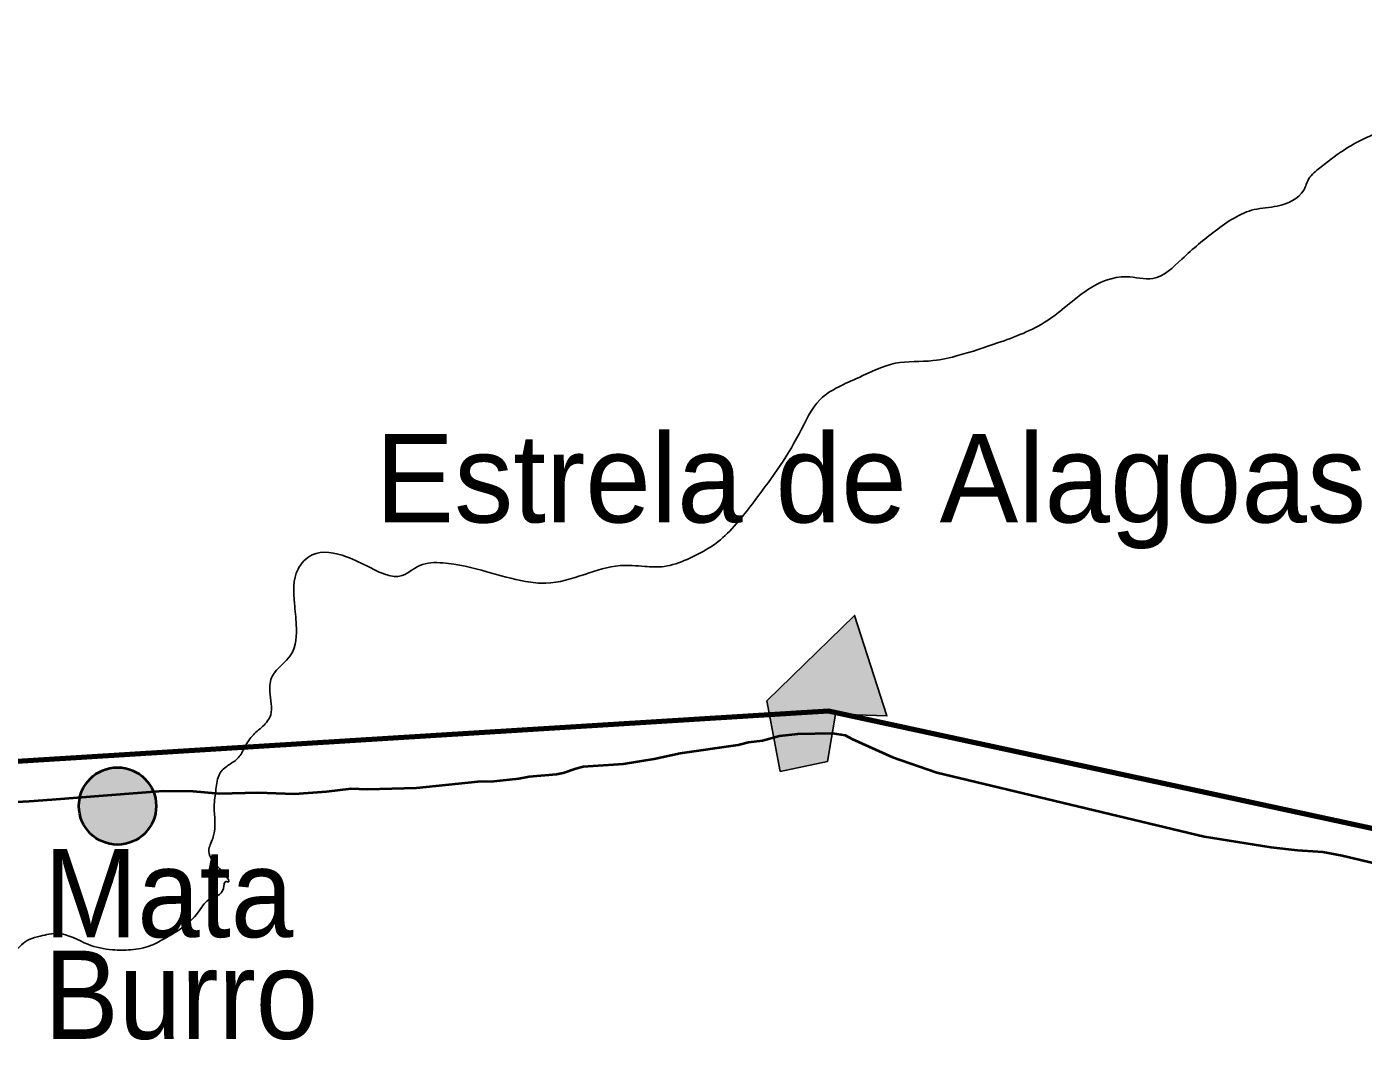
# Model space of a CAD drawing. Extents: x 553962 to 842807, y 8883888 to 9032388.
# Drawn here: x 740163 to 747736, y 8959924 to 8965692 of the extents above; entities that cross this region are included whole.
import ezdxf

# ---------------------------------------------------------------- set-up
doc = ezdxf.new("R2010")
doc.units = 0
doc.header["$LTSCALE"] = 200
for name, color, linetype, lineweight in [('12', 7, 'Continuous', 25), ('21', 7, 'Continuous', 25), ('24', 7, 'Continuous', 25), ('28', 7, 'Continuous', 40), ('41', 7, 'Continuous', 40)]:
    doc.layers.add(name, color=color, linetype=linetype, lineweight=lineweight)

msp = doc.modelspace()

# ---------------------------------------------------------------- hatches: boundary and pattern name
at = {"layer": '21'}
msp.add_hatch(color=256, dxfattribs=at).paths.add_polyline_path([(744356.4, 8961874.7), (744853, 8962358.3), (745037.2, 8961789.1), (744746.3, 8961798.3), (744699.8, 8961530.9), (744432.2, 8961475.3)])
at = {"layer": '41'}
msp.add_hatch(color=256, dxfattribs=at).paths.add_polyline_path([(740896.4, 8961278.9, 1), (740458.8, 8961278.9, 1)])

# ---------------------------------------------------------------- linework, layer by layer
at = {"layer": '12', "lineweight": 40}
for points in [[(740936, 8961365.4), (741106, 8961363.1), (741255.2, 8961350.5), (741473.6, 8961354.7), (741680.7, 8961348.7), (741862.6, 8961361.5), (742000.8, 8961377.5), (742091.8, 8961374.1), (742371.4, 8961382.9), (742720, 8961418.4), (742810.6, 8961420), (742952.1, 8961435.7), (743009.9, 8961446.4), (743164.6, 8961460), (743203.2, 8961467.8), (743274.7, 8961491.9), (743316.6, 8961501.9), (743544.7, 8961517.5), (743717.5, 8961546.2), (743866.4, 8961577.5), (744193.8, 8961624.7), (744252.3, 8961640.7), (744332.2, 8961650.4), (744428, 8961675.8), (744532, 8961687.5), (744726.7, 8961691.6), (744800.4, 8961679.5), (744837.6, 8961659.2), (745069.5, 8961555.1), (745320.6, 8961468.1), (746835.1, 8961107.2)], [(739168.8, 8961271.6), (739303.4, 8961273.3), (739754.5, 8961306.8), (739829, 8961307.2), (739953.4, 8961299), (740034.8, 8961298.8), (740177.7, 8961306.9), (740305.3, 8961315.9), (740936, 8961365.4)], [(746835.1, 8961107.2), (747212.1, 8961045.9), (747363, 8961029.3), (747506.6, 8961018.9), (747617.2, 8960998.5), (747824.8, 8960950.1)]]:
    msp.add_lwpolyline(points, dxfattribs=at)
at = {"layer": '21'}
msp.add_lwpolyline([(744356.4, 8961874.7), (744853, 8962358.3), (745037.2, 8961789.1), (744746.3, 8961798.3), (744699.8, 8961530.9), (744432.2, 8961475.3)], close=True, dxfattribs=at)
at = {"layer": '24'}
msp.add_spline([(738367.7, 8959924.4), (738437.2, 8960071.1), (738471.9, 8960121.3), (738537.5, 8960171.6), (738630.2, 8960202.5), (738765.3, 8960248.8), (738950.5, 8960322.2), (739124.2, 8960357), (739313.4, 8960368.5), (739359.7, 8960368.5), (739506.3, 8960291.3), (739610.6, 8960229.5), (739660.8, 8960198.6), (739703.2, 8960210.2), (739761.1, 8960275.8), (739826.7, 8960310.6), (739919.4, 8960314.5), (740031.3, 8960372.4), (740096.9, 8960453.5), (740178, 8960523), (740239.7, 8960542.3), (740340.1, 8960557.8), (740509.9, 8960496), (740648.9, 8960465.1), (740753.1, 8960465.1), (740865, 8960488.3), (740926.8, 8960519.2), (741135.2, 8960677.5), (741193.1, 8960747.1), (741278, 8960812.7), (741293.5, 8960851.3), (741300.5, 8960850.1), (741255.5, 8960925.1), (741195.5, 8961035.2), (741220.5, 8961105.2), (741225.5, 8961275.2), (741235.5, 8961375.3), (741255.5, 8961460.3), (741305.5, 8961510.3), (741355.4, 8961545.3), (741395.4, 8961605.3), (741440.4, 8961675.3), (741500.4, 8961730.4), (741545.4, 8961795.4), (741540.4, 8961925.4), (741555.4, 8962015.5), (741660.3, 8962135.5), (741690.3, 8962305.5), (741680.3, 8962425.6), (741700.3, 8962620.6), (741780.3, 8962700.7), (741975.2, 8962690.7), (742105.2, 8962630.6), (742195.2, 8962590.6), (742275.1, 8962580.6), (742390.1, 8962640.6), (742520.1, 8962655.6), (742770, 8962605.6), (742989.9, 8962550.6), (743104.8, 8962540.6), (743324.8, 8962590.6), (743524.7, 8962640.6), (743664.7, 8962635.6), (743774.6, 8962635.6), (743904.6, 8962675.7), (744079.5, 8962775.7), (744274.5, 8962990.7), (744539.4, 8963385.9), (744659.3, 8963580.9), (744879.3, 8963706), (745084.2, 8963786), (745299.1, 8963801), (745444.1, 8963831), (745664, 8963901), (745943.9, 8964026.1), (746173.8, 8964201.1), (746393.8, 8964276.1), (746543.7, 8964266.1), (746708.6, 8964376.2), (746898.6, 8964536.2), (747118.5, 8964656.2), (747248.5, 8964676.2), (747398.4, 8964766.3), (747428.4, 8964831.3), (747488.4, 8964891.3), (747623.3, 8964991.3), (747863.3, 8965106.4), (747993.2, 8965146.4), (748133.2, 8965221.4), (748228.1, 8965321.5), (748358.1, 8965451.5)], degree=3, dxfattribs=at)
at = {"layer": '28', "lineweight": 80}
msp.add_lwpolyline([(756666.9, 8960280.5), (753769.9, 8960761.1), (752238.8, 8960190.3), (744706.3, 8961816), (738249.1, 8961416.3), (734964.7, 8968490.1), (734839.6, 8970305.5)], dxfattribs=at)
at = {"layer": '41'}
msp.add_circle((740677.6, 8961278.9), 218.8, dxfattribs=at)

# ---------------------------------------------------------------- texts
msp.add_text('Estrela de Alagoas', height=500, dxfattribs=at).set_placement((742139.2, 8962884.6))
at = {"layer": '41', "width": 0.95}
for s, p in [('Mata', (740261, 8960536.3)), ('Burro', (740261, 8959960.5))]:
    msp.add_text(s, height=500, dxfattribs=at).set_placement(p)

doc.saveas('drawing.dxf')
